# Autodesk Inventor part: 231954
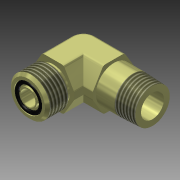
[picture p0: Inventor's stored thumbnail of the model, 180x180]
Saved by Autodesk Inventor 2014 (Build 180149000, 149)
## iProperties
Shininess: 20.0
Length Units: 11272
Angle Units: 11279
Time Units: 11290
Mass Units: 11286
Length Display Precision: 3
Angle Display Precision: 2
Company: Autodesk, Inc.
Created: 2002-05
Part Number: 231954
Material: Steel, Mild
Description: FITTING; EL-BC96-S
Document SubType Name: Modeling
Designer: Autodesk, Inc.
Density: 8.182 g/cm^3
Appearance: Yellow Zinc
Density: 0.0
Volumn: 0.0
Area: 0.0
PropertySet Name: Model Information
Control State: 0
Master: False
Checked Out: False
Last Check In By: JT
Last Check In Date: 2003-06-20
Title: FITTING; EL-BC96-S
Author: Autodesk, Inc.
Comments: -
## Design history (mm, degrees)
sketch "Sketch1"
  geometry: L1 (-9.525, 0)-(-9.525, 1.587); L2 (-9.525, 1.587)-(-4.763, 9.525); L3 (-4.763, 9.525)-(4.762, 9.525); L4 (4.762, 9.525)-(9.525, 1.587); L5 (9.525, 1.587)-(9.525, 0); L6 (-9.525, 0)-(0, 0); L7 (0, 0)-(9.525, 0); L8 (-9.525, -1.587)-(-9.525, 0); L9 (9.525, -1.587)-(9.525, 0); L10 (-9.525, -1.587)-(-4.763, -9.525); L11 (4.762, -9.525)-(9.525, -1.587); L12 (-4.763, -9.525)-(4.762, -9.525); C1 r 3.353 at (0, 0); 1 further point
  constraints: 24 end point, 4 equal length, 3 perpendicular, 2 horizontal, 2 vertical alignment, 1 centre point, 1 coincident, 1 collinear, 1 horizontal alignment
  dimensions: "d4" = 1.5875 distance of L1.start L1.end (= Flat_Spot); "d5" = 19.05 distance between parallel lines of L5 L1 (= Wrench_Flats_JJ); "d6" = 4.7625 distance from line of L3.end L5 (= 3 x Flat_Spot); "d7" = 9.525 distance from line of L3 point (0, 0) (= 0.5 x Wrench_Flats_JJ); "d8" = 4.7625 horizontal distance of L1.end L2.end (= 3 x Flat_Spot); "d9" = 9.525 distance from line of L1 point (0, 0) (= 0.5 x d5); "d119" = 6.7056 diameter of C1 (derived)
extrude "Body Side 1" new body sketch "Sketch1" distance "d10" = 13.6906 (= M - CC); taper "d11" = 0 deg
sketch "Sketch2"
  geometry: L1 (0, -9.525)-(-1.587, -9.525); L2 (-1.587, -9.525)-(-9.525, -4.763); L3 (-9.525, -4.763)-(-9.525, 4.763); L4 (-9.525, 4.763)-(-1.587, 9.525); L5 (-1.587, 9.525)-(0, 9.525); L6 (0, -9.525)-(1.587, -9.525); L7 (1.587, -9.525)-(9.525, -4.762); L8 (9.525, -4.762)-(9.525, 4.763); L9 (9.525, 4.763)-(1.587, 9.525); L10 (1.587, 9.525)-(0, 9.525); L11 (0, -9.525)-(0, 0); L12 (0, 0)-(0, 9.525); C1 r 5.156 at (0, 0); 1 further point
  constraints: 24 end point, 5 equal length, 3 horizontal, 2 perpendicular, 1 centre point, 1 coincident, 1 collinear, 1 vertical, 1 vertical alignment
  dimensions: "d21" = 1.5875 distance of L1.start L1.end (= Flat_Spot); "d22" = 19.05 distance between parallel lines of L5 L1 (= Wrench_Flats_JJ); "Flat_Spot_1" = 4.7625 vertical distance of L1.end L2.end (= 3 x Flat_Spot); "Flat_Spot_2" = 4.7625 vertical distance of L3.end L4.end (= 3 x Flat_Spot); "d25" = 9.525 distance from line of L3 point (0, 0) (= 0.5 x Wrench_Flats_JJ); "d26" = 9.525 distance from line of L1 point (0, 0) (= 0.5 x d22); "d120" = 10.3124 diameter of C1 (derived)
extrude "Body Side 2" join sketch "Sketch2" distance "d18" = 13.6906 (= M - CC); taper "d19" = 0 deg
sketch "Sketch3"
  geometry: L1 (0, 9.525)-(0, -9.525) reference; L2 (-4.762, 9.525)-(0, 9.525) reference; L3 (-9.525, 1.587)-(-4.762, 9.525) reference; L4 (-9.525, -1.587)-(-9.525, 1.587) reference; L5 (-4.763, -9.525)-(-9.525, -1.587) reference; L6 (0, -9.525)-(-4.763, -9.525) reference
revolve "Revolution1" sketch "Sketch3" stored, may be unused: angle "d27" = 90 deg
sketch "Sketch4"
  geometry: L1 (0, 0)-(0, 40.563); L2 (-3.353, 13.691)-(-7.607, 13.691); L3 (-7.607, 13.691)-(-7.607, 14.453); L4 (-7.607, 14.453)-(-8.731, 15.577); L5 (-8.731, 15.577)-(-8.731, 23.768); L6 (-8.731, 23.768)-(-7.607, 24.892); L7 (-7.607, 24.892)-(-6.299, 24.892); L8 (-6.299, 24.892)-(-6.299, 23.546); L9 (-6.299, 23.546)-(-3.886, 23.546); L10 (-3.886, 23.546)-(-3.886, 24.892); L11 (-3.886, 24.892)-(-3.353, 24.892); L12 (-3.353, 24.892)-(-3.353, 13.691); L13 (-7.607, 24.892)-(-7.607, 21.524)
  constraints: 26 end point, 5 perpendicular, 4 parallel, 2 collinear, 1 vertical
  dimensions: "d28" = 0.762 distance of L2.end L3.end (= Face_Seal_Undercut_Length_H); "d29" = 45 deg angle of L4 L5; "d30" = 11.2014 distance between parallel lines of L11 L2 (= CC); "d31" = 2.413 distance between parallel lines of L10 L8; "d32" = 6.7056 diameter of L12 L1 (= Face_Seal_ID); "d33" = 12.5984 diameter of L8 L1 (= Face_Seal_Groove_Dia); "d34" = 15.2146 diameter of L6.end L1 (= Face_Seal_Lip); "d35" = 17.4625 diameter of L5 L1 (= Face_Seal_Thread_OD); "d36" = 1.3462 distance between parallel lines of L7 L9; "d37" = 13.6906 distance from line of L2 L1.start (= M - CC)
revolve "Male Face-Seal" sketch "Sketch4" stored, may be unused: angle "d38" = 90 deg
thread "Male Face-Seal Thread" dims "d39" = 25.4, "d40" = 0
sketch "Sketch5"
  geometry: L1 (0, 0)-(0, 40.029); C1 r 0.794 at (-5.417, 24.34)
  constraints: 2 end point, 1 centre point, 1 vertical
  dimensions: "d41" = 1.5875 diameter of C1; "d42" = 24.33955 vertical distance of C1.centre L1.start (computed from M, d41); "d44" = 9.2456 dimension on C1 L1 (= Oring_Dia)
revolve "Male Face-Seal Oring" sketch "Sketch5" stored, may be unused: angle "d45" = 90 deg
fillet "Fillet1" dims "d80" = 1.524
sketch "Sketch14"
  geometry: L1 (-30.988, -7.773)-(-30.988, -5.156); L2 (-30.988, -5.156)-(-13.691, -5.156); L3 (-13.691, -5.156)-(-13.691, -8.139); L4 (0, 0)-(-24.609, 0); L5 (-30.988, -7.773)-(-22.098, -8.139); L6 (-22.098, -8.139)-(-13.691, -8.139)
  constraints: 12 end point, 2 perpendicular, 2 vertical, 1 parallel
  dimensions: "d121" = 13.6906 distance from line of L4.start L3 (derived); "d122" = 10.3124 diameter of L2 L4 (derived); "d123" = 15.54505 diameter of L1.start L4 (derived); "d124" = 16.27886 diameter of L6 L4 (derived); "d125" = 30.988 distance from line of L1 L4.start (derived); "d126" = 22.098 horizontal distance of L5.end L4.start (derived)
revolve "Revolution11" sketch "Sketch14" stored, may be unused: angle "d127" = 90 deg
thread "Thread4" dims "d128" = 25.4, "d129" = 0
body "Solid1"
other parameters: "CC" = 11.2014 [user parameter; used in 4 equation terms], "Face_Seal_Undercut_Length_H" = 0.762 [user parameter; used in 1 equation term], "Face_Seal_ID" = 6.7056 [user parameter; used in 1 equation term], "Face_Seal_Groove_Dia" = 12.5984 [user parameter; used in 1 equation term], "Face_Seal_Lip" = 15.2146 [user parameter; used in 1 equation term], "Face_Seal_Thread_OD" = 17.4625 [user parameter; used in 1 equation term], "Wrench_Flats_JJ" = 19.05 [user parameter; used in 4 equation terms], "Flat_Spot" = 1.5875 [user parameter; used in 6 equation terms], "M" = 24.892 [user parameter; used in 4 equation terms], "Oring_Dia" = 9.2456 [user parameter; used in 1 equation term], "D2" = 10.3124, "N1" = 30.988 [user parameter], "A" = 15.54505 [user parameter], "C" = 16.27886 [user parameter], "XX" = 22.098 [user parameter]
